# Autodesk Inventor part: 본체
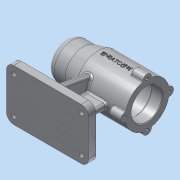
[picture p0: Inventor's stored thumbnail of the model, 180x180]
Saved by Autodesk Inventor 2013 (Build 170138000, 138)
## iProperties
Created: 2019-07
Part Number: 본체
Material: 알루미늄 6061
Document SubType Name: Modeling
Designer: Administrator
Density: 2.71 g/cm^3
Mass: 783.637 g
Surface Area: 620.522 cm^2
Volume: 289.165 cm^3
Author: Administrator
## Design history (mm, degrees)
sketch "스케치1"
  geometry: L1 (17.653, 2.338)-(42.653, 2.338); L2 (17.653, -22.662)-(17.653, 2.338); L3 (62.653, 7.338)-(129.653, 7.338); L4 (129.653, 7.338)-(129.653, -1.662); L5 (17.653, -22.662)-(60.653, -22.662); L6 (42.653, 2.338)-(62.653, 7.338); L7 (114.653, -1.662)-(129.653, -1.662); L8 (60.653, 1.338)-(114.653, 1.338); L9 (114.653, 1.338)-(114.653, -1.662); L10 (60.653, -22.662)-(60.653, 1.338); 2 further points
  constraints: 20 end point, 4 horizontal, 2 perpendicular, 1 parallel, 1 vertical alignment
  dimensions: "d5" = 25 distance of L2.start L1.start; "d6" = 25 distance from line of L1.end L2; "d7" = 45 distance from line of L3.start L2; "d8" = 112 distance between parallel lines of L2 L4; "d9" = 30 distance of L3.end point (129.653, -22.662); "d22" = 54 distance of L8.start L8.end; "d23" = 24 distance of L5.end L8.start; "d24" = 21 distance between parallel lines of L5 L7; "d25" = 15 distance of L7.start L4.end
revolve "회전1" sketch "스케치1" stored, may be unused: angle "d10" = 90 deg
fillet "모깎기1" dims "d11" = 10
fillet "모깎기2" dims "d26" = 3
hole "구멍1" diameter "d29" = 35; stored, may be unused: countersink angle "d33" = 90 deg, drill point angle "d35" = 0 deg; dims "d30" = 6, "d31" = 42, "d32" = 12, "d34" = 30, "d36" = 10, "d37" = 10
fillet "모깎기3" dims "d38" = 0.3
sketch "스케치2"
  geometry: C1 r 17.2 at (0, 0) reference; 1 further point
hole "구멍2" sketch "스케치2" at (0, 0) diameter "d39" = 21; stored, may be unused: countersink angle "d43" = 90 deg, drill point angle "d45" = 0 deg; dims "d40" = 6, "d41" = 32, "d42" = 4, "d44" = 7
fillet "모깎기4" dims "d46" = 0.3
fillet "모깎기5" dims "d47" = 3
sketch "스케치3"
  geometry: L1 (129.653, -52.662)-(129.653, 7.338) reference; L2 (129.653, -102.662)-(17.653, -102.662); L3 (17.653, -102.662)-(17.653, -92.662); L4 (17.653, -92.662)-(129.653, -92.662); L5 (129.653, -92.662)-(129.653, -102.662); L6 (27.653, 2.338)-(42.653, 2.338) reference; L7 (42.653, 2.338)-(62.653, 7.338) reference; L8 (62.653, 7.338)-(129.653, 7.338) reference; L9 (129.653, 7.338)-(129.653, -1.662) reference; L10 (129.653, -1.662)-(114.653, -1.662) reference; L11 (111.653, 1.338)-(63.653, 1.338) reference; L12 (60.653, -1.662)-(48.953, -1.662) reference; L13 (48.653, -1.962)-(48.653, -5.162) reference; L14 (48.653, -5.162)-(30.953, -5.162) reference; L15 (30.653, -5.462)-(30.653, -6.662) reference; L16 (30.653, -6.662)-(26.953, -6.662) reference; L17 (26.653, -6.962)-(26.653, -12.162) reference; L18 (23.653, -15.162)-(23.653, -30.162) reference; L19 (26.653, -33.162)-(26.653, -38.362) reference; L20 (26.953, -38.662)-(30.653, -38.662) reference; L21 (30.653, -38.662)-(30.653, -39.862) reference; L22 (30.953, -40.162)-(48.653, -40.162) reference; L23 (48.653, -40.162)-(48.653, -43.362) reference; L24 (48.953, -43.662)-(60.653, -43.662) reference; L25 (63.653, -46.662)-(111.653, -46.662) reference; L26 (114.653, -43.662)-(129.653, -43.662) reference; L27 (129.653, -43.662)-(129.653, -52.662) reference; L28 (129.653, -52.662)-(62.653, -52.662) reference; L29 (62.653, -52.662)-(42.653, -47.662) reference; L30 (42.653, -47.662)-(27.653, -47.662) reference; L31 (17.653, -37.662)-(17.653, -7.662) reference; L32 (17.653, -37.662)-(17.653, -7.662) reference; A1 r 10 centre (27.653, -7.662) between (27.653, 2.338) and (17.653, -7.662) reference; A2 r 3 centre (111.653, -1.662) between (114.653, -1.662) and (111.653, 1.338) reference; A3 r 3 centre (63.653, -1.662) between (63.653, 1.338) and (60.653, -1.662) reference; A4 r 0.3 centre (48.953, -1.962) between (48.953, -1.662) and (48.653, -1.962) reference; A5 r 0.3 centre (30.953, -5.462) between (30.953, -5.162) and (30.653, -5.462) reference; A6 r 0.3 centre (26.953, -6.962) between (26.953, -6.662) and (26.653, -6.962) reference; A7 r 3 centre (26.653, -15.162) between (26.653, -12.162) and (23.653, -15.162) reference; A8 r 3 centre (26.653, -30.162) between (23.653, -30.162) and (26.653, -33.162) reference; A9 r 0.3 centre (26.953, -38.362) between (26.653, -38.362) and (26.953, -38.662) reference; A10 r 0.3 centre (30.953, -39.862) between (30.653, -39.862) and (30.953, -40.162) reference; A11 r 0.3 centre (48.953, -43.362) between (48.653, -43.362) and (48.953, -43.662) reference; A12 r 3 centre (63.653, -43.662) between (60.653, -43.662) and (63.653, -46.662) reference; A13 r 3 centre (111.653, -43.662) between (111.653, -46.662) and (114.653, -43.662) reference; A14 r 10 centre (27.653, -37.662) between (17.653, -37.662) and (27.653, -47.662) reference; 2 further points
  constraints: 8 end point, 2 parallel, 1 horizontal, 1 midpoint, 1 perpendicular
  dimensions: "d49" = 112 distance of L3.end L4.end; "d50" = 10 distance of L2.end L3.end; "d51" = 80 distance from line of point (17.653, -22.662) L2
extrude "돌출1" join sketch "스케치3" distance "d52" = 35; taper "d54" = 0 deg; dims "d53" = 35, "d55" = 0
fillet "모깎기6" dims "d56" = 10
hole "구멍3" diameter "d59" = 6; stored, may be unused: countersink angle "d63" = 90 deg, drill point angle "d65" = 0 deg; dims "d57" = 10, "d58" = 10, "d60" = 6, "d61" = 32, "d62" = 4, "d64" = 10
sketch "스케치4"
  geometry: C1 r 21 at (0, 0) reference; C2 r 6 at (0, 30); C3 r 6 at (-30, 0); C4 r 6 at (0, -30); C5 r 6 at (30, 0); 2 further points
  constraints: 4 centre point, 1 vertical alignment, 10 other
  dimensions: "d72" = 12 diameter of C2; "d75" = 360 deg dimension on C1.centre C2.centre (derived)
extrude "돌출2" join sketch "스케치4" distance "d77" = 16; taper "d78" = 0 deg
fillet "모깎기7" dims "d79" = 1
fillet "모깎기9" dims "d81" = 1
fillet "모깎기10" dims "d82" = 1
fillet "모깎기11" dims "d83" = 1
chamfer "모따기1" distance "d84" = 1; stored, may be unused: second distance "d85" = 2, angle "d86" = 45 deg
hole "구멍4" diameter "d89" = 3.459; stored, may be unused: countersink angle "d93" = 90 deg, drill point angle "d95" = 118 deg; dims "d87" = 10, "d88" = 10, "d90" = 8, "d91" = 32, "d92" = 4, "d94" = 11
node "작업 평면1"
sketch "스케치5"
  geometry: L1 (37.653, -92.662)-(104.653, -92.662); L2 (17.653, -102.662)-(17.653, -92.662) reference; L3 (129.653, -92.662)-(129.653, -102.662) reference; L4 (37.653, -92.662)-(123.327, -92.662); L5 (27.653, 2.338)-(42.653, 2.338) reference; L6 (42.653, 2.338)-(62.653, 7.338) reference; L7 (62.653, 7.338)-(112.653, 7.338) reference; L8 (113.653, 8.338)-(113.653, 12.338) reference; L9 (114.653, 13.338)-(129.653, 13.338) reference; L10 (129.653, 13.338)-(129.653, 9.068) reference; L11 (129.653, 9.068)-(118.653, 9.068) reference; L12 (118.653, 9.068)-(117.614, 7.338) reference; L13 (117.614, 7.338)-(118.653, 5.609) reference; L14 (118.653, 5.609)-(129.653, 5.609) reference; L15 (129.653, 5.609)-(129.653, -0.662) reference; L16 (129.653, -0.662)-(128.653, -1.662) reference; L17 (128.653, -1.662)-(114.653, -1.662) reference; L18 (111.653, 1.338)-(63.653, 1.338) reference; L19 (60.653, -1.662)-(48.953, -1.662) reference; L20 (48.653, -1.962)-(48.653, -5.162) reference; L21 (48.653, -5.162)-(30.953, -5.162) reference; L22 (30.653, -5.462)-(30.653, -6.662) reference; L23 (30.653, -6.662)-(26.953, -6.662) reference; L24 (26.653, -6.962)-(26.653, -12.162) reference; L25 (23.653, -15.162)-(23.653, -30.162) reference; L26 (26.653, -33.162)-(26.653, -38.362) reference; L27 (26.953, -38.662)-(30.653, -38.662) reference; L28 (30.653, -38.662)-(30.653, -39.862) reference; L29 (30.953, -40.162)-(48.653, -40.162) reference; L30 (48.653, -40.162)-(48.653, -43.362) reference; L31 (48.953, -43.662)-(60.653, -43.662) reference; L32 (63.653, -46.662)-(111.653, -46.662) reference; L33 (114.653, -43.662)-(128.653, -43.662) reference; L34 (128.653, -43.662)-(129.653, -44.662) reference; L35 (129.653, -44.662)-(129.653, -50.932) reference; L36 (129.653, -50.932)-(118.653, -50.932) reference; L37 (118.653, -50.932)-(117.614, -52.662) reference; L38 (117.614, -52.662)-(118.653, -54.391) reference; L39 (118.653, -54.391)-(129.653, -54.391) reference; L40 (129.653, -54.391)-(129.653, -58.662) reference; L41 (129.653, -58.662)-(114.653, -58.662) reference; L42 (113.653, -57.662)-(113.653, -53.662) reference; L43 (112.653, -52.662)-(62.653, -52.662) reference; L44 (62.653, -52.662)-(42.653, -47.662) reference; L45 (42.653, -47.662)-(27.653, -47.662) reference; L46 (17.653, -37.662)-(17.653, -7.662) reference; L47 (17.653, -102.662)-(17.653, -92.662) reference; L48 (17.653, -92.662)-(129.653, -92.662) reference; L49 (129.653, -92.662)-(129.653, -102.662) reference; L50 (129.653, -102.662)-(17.653, -102.662) reference; L51 (104.653, -92.662)-(104.653, -50.162); L52 (53.122, -50.162)-(104.653, -50.162); L53 (37.653, -92.662)-(53.122, -50.162); A1 r 10 centre (27.653, -7.662) between (27.653, 2.338) and (17.653, -7.662) reference; A2 r 1 centre (112.653, 8.338) between (112.653, 7.338) and (113.653, 8.338) reference; A3 r 1 centre (114.653, 12.338) between (114.653, 13.338) and (113.653, 12.338) reference; A4 r 3 centre (111.653, -1.662) between (114.653, -1.662) and (111.653, 1.338) reference; A5 r 3 centre (63.653, -1.662) between (63.653, 1.338) and (60.653, -1.662) reference; A6 r 0.3 centre (48.953, -1.962) between (48.953, -1.662) and (48.653, -1.962) reference; A7 r 0.3 centre (30.953, -5.462) between (30.953, -5.162) and (30.653, -5.462) reference; A8 r 0.3 centre (26.953, -6.962) between (26.953, -6.662) and (26.653, -6.962) reference; A9 r 3 centre (26.653, -15.162) between (26.653, -12.162) and (23.653, -15.162) reference; A10 r 3 centre (26.653, -30.162) between (23.653, -30.162) and (26.653, -33.162) reference; A11 r 0.3 centre (26.953, -38.362) between (26.653, -38.362) and (26.953, -38.662) reference; A12 r 0.3 centre (30.953, -39.862) between (30.653, -39.862) and (30.953, -40.162) reference; A13 r 0.3 centre (48.953, -43.362) between (48.653, -43.362) and (48.953, -43.662) reference; A14 r 3 centre (63.653, -43.662) between (60.653, -43.662) and (63.653, -46.662) reference; A15 r 3 centre (111.653, -43.662) between (111.653, -46.662) and (114.653, -43.662) reference; A16 r 1 centre (114.653, -57.662) between (113.653, -57.662) and (114.653, -58.662) reference; A17 r 1 centre (112.653, -53.662) between (113.653, -53.662) and (112.653, -52.662) reference; A18 r 10 centre (27.653, -37.662) between (17.653, -37.662) and (27.653, -47.662) reference; 1 further point
  constraints: 10 end point, 1 horizontal, 1 parallel, 1 perpendicular
  dimensions: "d104" = 20 distance from line of L1.start L2; "d105" = 25 distance from line of L3 L1.end; "d107" = 110 deg angle of L48 L53
extrude "돌출3" join sketch "스케치5" distance "d108" = 4; taper "d109" = 0 deg; dims "d110" = 4, "d111" = 0
fillet "모깎기12" dims "d112" = 3
node "작업 평면2"
sketch "스케치6"
  geometry: L1 (-53, 10)-(-44.654, 57.334); L2 (-53, 10)-(-16.134, 10); L3 (0, 10)-(62.345, 10); L4 (3, 10)-(-5.346, 57.334); L5 (3, 10)-(68.522, 10); L6 (-53, 10)-(3, 10); A1 r 30 centre (-25, 80) between (-44.654, 57.334) and (-5.346, 57.334); 1 further point
  constraints: 12 end point, 3 horizontal, 2 point on circle, 1 centre point
  dimensions: "d116" = 80 deg angle of L2 L1; "d118" = 100 deg angle of L5 L4
fillet "모깎기14" dims "d124" = 3
extrude "돌출5" join sketch "스케치6" stored distance "d125" = 8; taper "d126" = 0 deg
fillet "모깎기15" dims "d127" = 3
node "작업 평면3"
sketch "스케치7"
  geometry: L1 (33.5, 5.998)-(33.5, -5.998) reference; 3 further points
  constraints: 1 horizontal alignment, 1 midpoint, 1 other
  dimensions: "d128" = 42 distance from line of L1 point (-8.5, 0)
feature "엠보싱1" sketch "스케치7" dims "d5" = 25, "d6" = 25, "d7" = 45, "d8" = 112, "d9" = 30, "d22" = 54, "d23" = 24, "d24" = 21, "d25" = 15, "d31" = 42, "d129" = 0.5, "d130" = 0
node "솔리드1"
pattern_linear "직사각형 패턴1" dims "d68" = 50, "d71" = 92
pattern_circular "원형 패턴1" dims angle "d97" = 360 deg
node "절단 모서리 투영1"
node "절단 모서리 투영3"
other parameters: "d106" = 70 deg, "d117" = 100 deg
